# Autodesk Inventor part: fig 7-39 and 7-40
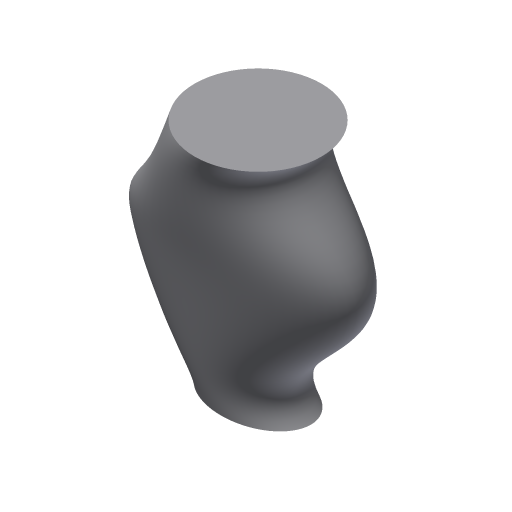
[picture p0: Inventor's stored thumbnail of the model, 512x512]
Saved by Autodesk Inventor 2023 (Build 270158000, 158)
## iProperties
Part Number: fig 7-39 and 7-40
Document SubType Name: Modeling
Created: 2002-12
Designer: deepak
Density: 1 g/cm^3
Material: Generic
Appearance: Default
Control State: 0
Master: False
Checked Out: False
Shininess: 64.0
Length Units: 11269
Angle Units: 11279
Time Units: 11290
Mass Units: 11283
Length Display Precision: 3
Angle Display Precision: 2
Compacted: True
Density: 0.0
Volumn: 0.0
Area: 0.0
PropertySet Name: Model Information
Author: deepak
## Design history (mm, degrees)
sketch "Sketch1"
  geometry: 2 further points; 1 other entity
  constraints: 1 coincident, 3 other
workplane "Work Plane1"
workplane "Work Plane2"
sketch "Sketch3"
  geometry: C1 r 60 at (0, 0); 1 further point
  constraints: 1 centre point, 1 coincident, 1 other
sketch "Sketch4"
  geometry: 8 further points
  constraints: 8 other
sketch "Sketch5"
  geometry: 6 further points
  constraints: 6 other
sketch "Sketch6"
  geometry: 6 further points
  constraints: 6 other
  dimensions: "d20" = 35 distance of point (0, 0) point (-35, 0); "d21" = 0 vertical distance of point (0, 0) point (-35, 0); "d22" = 225 vertical distance of point (0, 0) point (-60, 225); "d23" = 60 horizontal distance of point (0, 0) point (-60, 225); "d24" = 100 horizontal distance of point (0, 0) point (-100, 125); "d25" = 125 vertical distance of point (0, 0) point (-100, 125)
loft "Loft3" dims "d42" = 0, "d43" = 90 deg, "d44" = 0, "d45" = 90 deg, "d46" = 0, "d47" = 90 deg, "d48" = 0, "d49" = 90 deg
node "Sketch7"
sketch "Sketch8"
  geometry: 1 further point
body "Solid1"
other parameters: "d5" = 125
